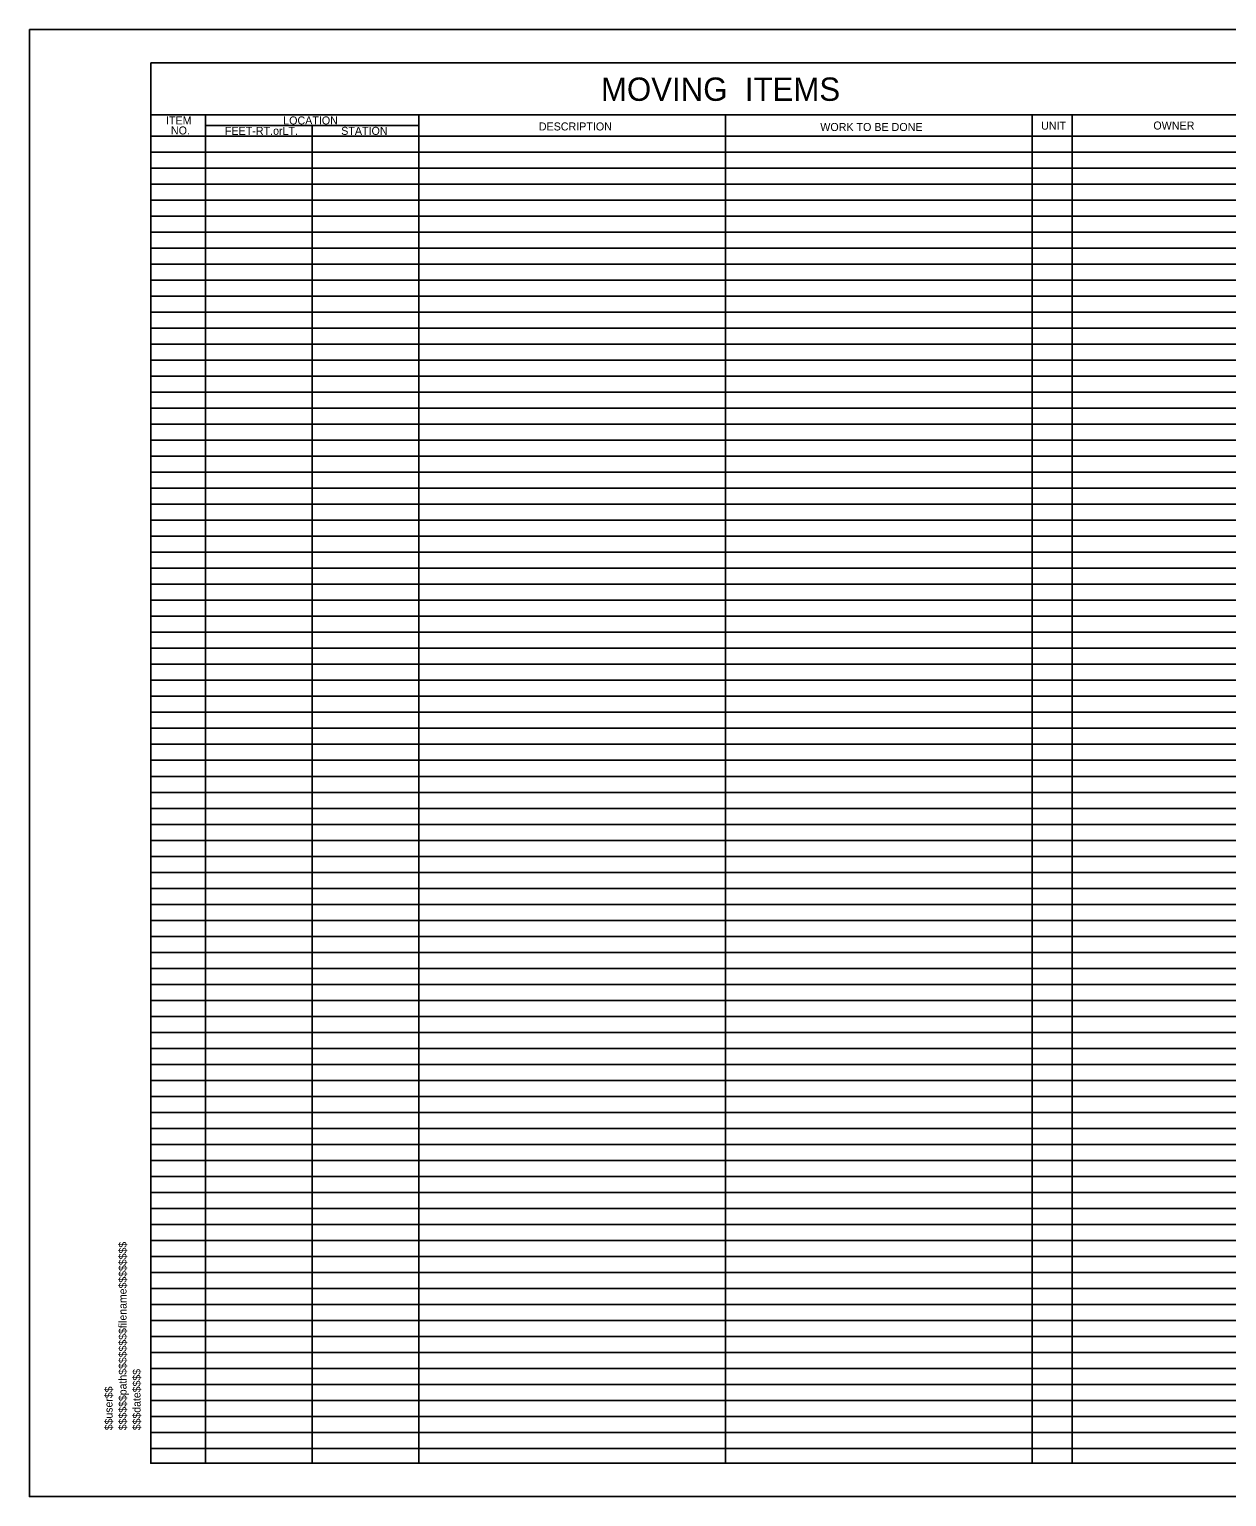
# Model space of a CAD drawing. Extents: x 8134 to 11793, y 3225 to 13425.
# Drawn here: x 9987 to 10884, y 6625 to 7725 of the extents above; entities that cross this region are included whole.
import ezdxf

# ---------------------------------------------------------------- set-up
doc = ezdxf.new("R2010")
doc.units = 0
for name, color, linetype in [('RD_SHT_Bndy', 7, 'Continuous'), ('RD_SHT_ID', 7, 'Continuous'), ('RD_SHT_IplotShp', 7, 'Continuous'), ('RD_SHT_TX', 7, 'Continuous')]:
    doc.layers.add(name, color=color, linetype=linetype)

msp = doc.modelspace()

# ---------------------------------------------------------------- linework, layer by layer
at = {"layer": 'RD_SHT_Bndy'}
for p, q in [((10000, 7725), (11760, 7725)), ((11760, 7725), (10000, 7725)), ((11752.5, 7661), (10077.5, 7661)), ((10118.7, 7661), (10118.7, 6650)), ((10278.7, 7661), (10278.7, 6650)), ((10508.7, 7660.9), (10508.7, 6650)), ((10738.7, 7661), (10738.7, 6650)), ((10768.7, 7661), (10768.7, 6650)), ((11752.5, 7645), (10077.5, 7645)), ((10278.7, 7653), (10118.7, 7653)), ((10198.7, 7653), (10198.7, 6650)), ((11752.5, 7633), (10077.5, 7633)), ((11752.5, 7621), (10077.5, 7621)), ((11752.5, 7609), (10077.5, 7609)), ((11752.5, 7597), (10077.5, 7597)), ((11752.5, 7585), (10077.5, 7585)), ((11752.5, 7573), (10077.5, 7573)), ((11752.5, 7561), (10077.5, 7561)), ((11752.5, 7549), (10077.5, 7549)), ((11752.5, 7537), (10077.5, 7537)), ((11752.5, 7525), (10077.5, 7525)), ((11752.5, 7513), (10077.5, 7513)), ((11752.5, 7501), (10077.5, 7501)), ((11752.5, 7489), (10077.5, 7489)), ((11752.5, 7477), (10077.5, 7477)), ((11752.5, 7465), (10077.5, 7465)), ((11752.5, 7453), (10077.5, 7453)), ((11752.5, 7441), (10077.5, 7441)), ((11752.5, 7429), (10077.5, 7429)), ((11752.5, 7417), (10077.5, 7417)), ((11752.5, 7405), (10077.5, 7405)), ((11752.5, 7393), (10077.5, 7393)), ((11752.5, 7381), (10077.5, 7381)), ((11752.5, 7369), (10077.5, 7369)), ((11752.5, 7357), (10077.5, 7357)), ((11752.5, 7345), (10077.5, 7345)), ((11752.5, 7333), (10077.5, 7333)), ((11752.5, 7321), (10077.5, 7321)), ((11752.5, 7309), (10077.5, 7309)), ((11752.5, 7297), (10077.5, 7297)), ((11752.5, 7285), (10077.5, 7285)), ((11752.5, 7273), (10077.5, 7273)), ((11752.5, 7261), (10077.5, 7261)), ((11752.5, 7249), (10077.5, 7249)), ((11752.5, 7237), (10077.5, 7237)), ((11752.5, 7225), (10077.5, 7225)), ((11752.5, 7213), (10077.5, 7213)), ((11752.5, 7201), (10077.5, 7201)), ((11752.5, 7189), (10077.5, 7189)), ((11752.5, 7177), (10077.5, 7177)), ((11752.5, 7165), (10077.5, 7165)), ((11752.5, 7153), (10077.5, 7153)), ((11752.5, 7141), (10077.5, 7141)), ((11752.5, 7129), (10077.5, 7129)), ((11752.5, 7117), (10077.5, 7117)), ((11752.5, 7105), (10077.5, 7105)), ((11752.5, 7093), (10077.5, 7093)), ((11752.5, 7081), (10077.5, 7081)), ((11752.5, 7069), (10077.5, 7069)), ((11752.5, 7057), (10077.5, 7057)), ((11752.5, 7045), (10077.5, 7045)), ((11752.5, 7033), (10077.5, 7033)), ((11752.5, 7021), (10077.5, 7021)), ((11752.5, 7009), (10077.5, 7009)), ((11752.5, 6997), (10077.5, 6997)), ((11752.5, 6985), (10077.5, 6985)), ((11752.5, 6973), (10077.5, 6973)), ((11752.5, 6961), (10077.5, 6961)), ((11752.5, 6949), (10077.5, 6949)), ((11752.5, 6937), (10077.5, 6937)), ((11752.5, 6925), (10077.5, 6925)), ((11752.5, 6913), (10077.5, 6913)), ((11752.5, 6901), (10077.5, 6901)), ((11752.5, 6889), (10077.5, 6889)), ((11752.5, 6877), (10077.5, 6877)), ((11752.5, 6865), (10077.5, 6865)), ((11752.5, 6853), (10077.5, 6853)), ((11752.5, 6841), (10077.5, 6841)), ((11752.5, 6829), (10077.5, 6829)), ((11752.5, 6817), (10077.5, 6817)), ((11752.5, 6805), (10077.5, 6805)), ((11752.5, 6793), (10077.5, 6793)), ((11752.5, 6781), (10077.5, 6781)), ((11752.5, 6769), (10077.5, 6769)), ((11608.5, 6757), (10077.5, 6757)), ((11608.5, 6745), (10077.5, 6745)), ((11608.5, 6733), (10077.5, 6733)), ((11608.5, 6721), (10077.5, 6721)), ((11608.5, 6709), (10077.5, 6709)), ((11608.5, 6697), (10077.5, 6697)), ((11608.5, 6685), (10077.5, 6685)), ((11608.5, 6673), (10077.5, 6673)), ((11608.5, 6661), (10077.5, 6661)), ((10000, 6625), (11760, 6625)), ((11760, 6625), (10000, 6625))]:
    msp.add_line(p, q, dxfattribs=at)
msp.add_lwpolyline([(10077.5, 7700), (11752.5, 7700), (11752.5, 6650), (10077.5, 6650)], close=True, dxfattribs=at)
at = {"layer": 'RD_SHT_IplotShp'}
msp.add_lwpolyline([(9986.5, 7725), (11782.5, 7725), (11782.5, 6625), (9986.5, 6625)], close=True, dxfattribs=at)

# ---------------------------------------------------------------- texts
at = {"layer": 'RD_SHT_ID'}
for s, p in [('$$$$$$path$$$$$$$$filename$$$$$$$$', (10059.4, 6674.8)), ('$$$date$$$$', (10069.9, 6674.8)), ('$$user$$', (10048.9, 6674.8))]:
    msp.add_text(s, height=5.88, rotation=90, dxfattribs=at).set_placement(p)
at = {"layer": 'RD_SHT_TX'}
for s, height, p in [('MOVING  ITEMS', 17.5, (10415.2, 7671.4)), ('ITEM', 6, (10089, 7653.7)), ('LOCATION', 6, (10176.9, 7653.7)), ('NO.', 6, (10092.7, 7646.2)), ('FEET-RT.orLT.', 6, (10133.2, 7645.9)), ('STATION', 6, (10220.4, 7645.9)), ('DESCRIPTION', 6, (10368.6, 7649.2)), ('WORK TO BE DONE', 6, (10579.7, 7648.8)), ('UNIT', 6, (10745.3, 7649.8)), ('OWNER', 6, (10829.5, 7649.9))]:
    msp.add_text(s, height=height, dxfattribs=at).set_placement(p)

doc.saveas('drawing.dxf')
